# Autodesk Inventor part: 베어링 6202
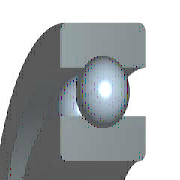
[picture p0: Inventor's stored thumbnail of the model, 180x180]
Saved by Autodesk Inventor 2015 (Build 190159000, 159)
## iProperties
IsCustomPart: 1
Created: 2015-12
Part Number: 베어링 6202
Material: 강철, 연강
Description: 깊은 그루브 볼 베어링
Document SubType Name: Modeling
Standard: KS B 2023
Designer: mdu
Standards Organization: KS
Language: ko-KR
Size Designation: 6202 - 15 x 35 x 11
Categories: <MemberInstance><Categories><Category DisplayName="샤프트 부품" InternalName="7f7aeb1f-a693-4053-b835-cee3144e0d98" Mnemonic="SHFT"><Category DisplayName="베어링" Inter
Density: 7.86 g/cm^3
Mass: 45.8725 g
Surface Area: 51.5584 cm^2
Volume: 5.83619 cm^3
Appearance: 노란색
Author: mdu
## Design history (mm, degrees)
sketch "스케치" dims "d0" = 5.2 (= -0.26 x WD + 0.26 x BD)
  geometry: L1 (2.9, 12.5)-(8.1, 12.5); L2 (5.5, 12.5)-(5.5, 9.9); L3 (5.5, 12.5)-(5.5, 15.1); L4 (3.568, 10.76)-(0, 10.76); L5 (0, 7.5)-(11, 7.5); L6 (3.568, 14.24)-(0, 14.24); L7 (0, 17.5)-(11, 17.5); L8 (11, 7.5)-(11, 10.76); L9 (7.432, 10.76)-(11, 10.76); L10 (7.432, 14.24)-(11, 14.24); L11 (11, 17.5)-(11, 14.24); L12 (-1.4, 0)-(8.4, 0) reference; L13 (0, -0.3)-(0, 5.3) reference
  constraints: 22 end point, 4 point on line, 2 collinear, 2 perpendicular, 2 symmetric about line, 1 midpoint, 1 parallel, 14 other
  dimensions: "d9" = 15 diameter of L5 L12 (= WD); "d11" = 35 diameter of L7 L12 (= BD); "d12" = 11 distance between parallel lines of L8 L13 (= KB); "d13" = 21.52 diameter of L9 L12 (= 0.326 x BD + 0.674 x WD)
revolve "본체" stored, may be unused: angle "d6" = 90 deg
revolve "볼" stored, may be unused: angle "d7" = 90 deg
pattern_circular "IDS_ARRAYBALL[SIMPL:T]" dims angle "d3" = 360 deg
body "Solid1"
fillet "모깎기1" dims "d1" = 0.6 (= KRS)
other parameters: "WD" = 15 [user parameter; used in 5 equation terms], "BD" = 35 [user parameter; used in 5 equation terms], "KB" = 11 [user parameter; used in 1 equation term], "KRS" = 0.6 [user parameter; used in 1 equation term], "d4" = 0, "d5" = 0, "d8" = 0, "d14" = 0, "d15" = 0, "BBA" = 0 [user parameter], "BC0" = 3750000 [user parameter], "BC" = 7800000 [user parameter], "BR" = 17.5 (= 0.5 x BD) [user parameter], "WR" = 7.5 (= 0.5 x WD) [user parameter]
